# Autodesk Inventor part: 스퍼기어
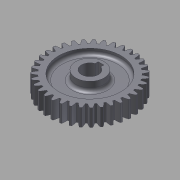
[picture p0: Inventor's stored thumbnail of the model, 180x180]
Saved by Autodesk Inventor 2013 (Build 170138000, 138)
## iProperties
Created: 2013-08
Part Number: 스퍼기어
Material: 강
Document SubType Name: Modeling
Designer: 한국산업디자인학원
Categories: <?xml version="1.0" encoding="UTF-16"?> <MemberInstance><Categories><FamilyTemplate><FamilyTemplateParameter ValueType="xs:double" Id="1" ObjectReferenceKey="da
Density: 1 g/cm^3
CustomPartVersion: 1
Author: 한국산업디자인학원
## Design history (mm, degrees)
sketch "Sketch1"
  geometry: C1 r 37 at (0, 0)
  constraints: 1 centre point
  dimensions: "d0" = 74 diameter of C1 (= da_da)
extrude "Extrusion1" new body sketch "Sketch1" distance "d1" = 15 (= da_b); taper "d2" = 0 deg
workplane "Work Plane2"
feature "피치 지름" dims "d4" = 10, "d5" = 0
workplane "Work Plane8"
workplane "Work Plane9"
feature "스퍼 기어" dims "da_b" = 15, "da_d" = 70, "da_aw" = 70, "da_da" = 74, "da_df" = 65, "da_dw" = 70, angle "da_beta" = 0 deg, "da_lefttooth" = 0, "da_righttooth" = 0
sketch "스케치4"
  geometry: L1 (-35, 0)-(-35, 15) reference; L2 (-35, 15)-(35, 15) reference; L3 (35, 15)-(35, 0) reference; L4 (35, 0)-(-35, 0) reference; L5 (0, 15)-(0, 0); L6 (-27.5, 15)-(-27.5, 10); L7 (-27.5, 10)-(-12.5, 10); L8 (-12.5, 10)-(-12.5, 15); L9 (-27.5, 0)-(-27.5, 5); L10 (-27.5, 5)-(-12.5, 5); L11 (-12.5, 5)-(-12.5, 0); 4 further points
  constraints: 14 end point, 5 midpoint, 5 perpendicular, 4 point on line, 2 parallel, 2 vertical alignment
  dimensions: "d49" = 55 diameter of L6 L5; "d51" = 25 diameter of L8 L5; "d52" = 5 distance between parallel lines of L2 L7; "d53" = 5 distance between parallel lines of L4 L10
revolve "회전1" sketch "스케치4" stored, may be unused: angle "d54" = 90 deg
hole "구멍1" diameter "d57" = 15; stored, may be unused: countersink angle "d61" = 90 deg, drill point angle "d63" = 0 deg; dims "d55" = 10, "d56" = 10, "d58" = 6, "d59" = 4, "d60" = 2, "d62" = 8
sketch "스케치5"
  geometry: L1 (-2.5, 9.8)-(-2.5, 7.071); L2 (-2.5, 9.8)-(2.5, 9.8); L3 (2.5, 9.8)-(2.5, 7.071); C1 r 12.5 at (0, 0) reference; A1 r 7.5 centre (0, 0) between (-2.5, 7.071) and (2.5, 7.071) reference
  constraints: 6 end point, 2 perpendicular, 2 point on circle, 1 parallel, 1 vertical
  dimensions: "d68" = 9.8 distance from line of L2 A1.centre; "d69" = 5 distance between parallel lines of L3 L1
extrude "돌출2" join sketch "스케치5" distance "d64" = 3; taper "d65" = 0 deg
extrude "돌출3" join sketch "스케치5" distance "d66" = 28; taper "d67" = 0 deg
extrude "돌출4" cut sketch "스케치5" stored distance "d70" = 28; taper "d71" = 0 deg
fillet "모깎기1" dims "d72" = 3
body "Solid1"
sketch "Sketch2"
  geometry: C1 r 37 at (0, 0) reference; C2 r 35 at (0, 0)
  constraints: 1 centre point, 1 coincident
  dimensions: "d3" = 70 diameter of C2 (= da_dw)
body "Srf1"
node "절단 모서리 투영1"
other parameters: "d17" = 0, "d34" = 0.8976 (computed from da_z), "d39" = 0, "d41" = 0, "d47" = 0, "d48" = 0
